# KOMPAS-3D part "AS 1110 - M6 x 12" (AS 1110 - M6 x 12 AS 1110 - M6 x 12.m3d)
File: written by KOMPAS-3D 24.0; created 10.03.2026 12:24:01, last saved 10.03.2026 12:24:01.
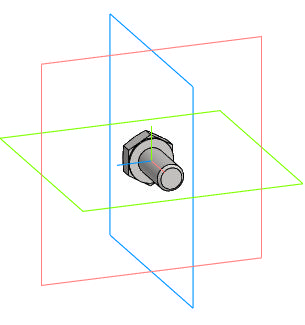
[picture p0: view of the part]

Document properties: Автор: R2D2; Полное имя файла: E:\Работа\Зайцев\BV3232P(4pc)-FP-3WL-F-ISO-H Кран шаровой DN.ru Ду15-100 Ру16\DN32\исходные материалы\AS 1110 - M6 x 12 AS 1110 - M6 x 12.m3d

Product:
- Body: Solid1  | qty 1
- Part/product: AS 1110 - M6 x 12
    Комментарий: Болты и винты   шестигранные точные   метрические ISO
    additional columns: Сталь, мягкая

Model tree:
1. Solid1  (labels: Solid1)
